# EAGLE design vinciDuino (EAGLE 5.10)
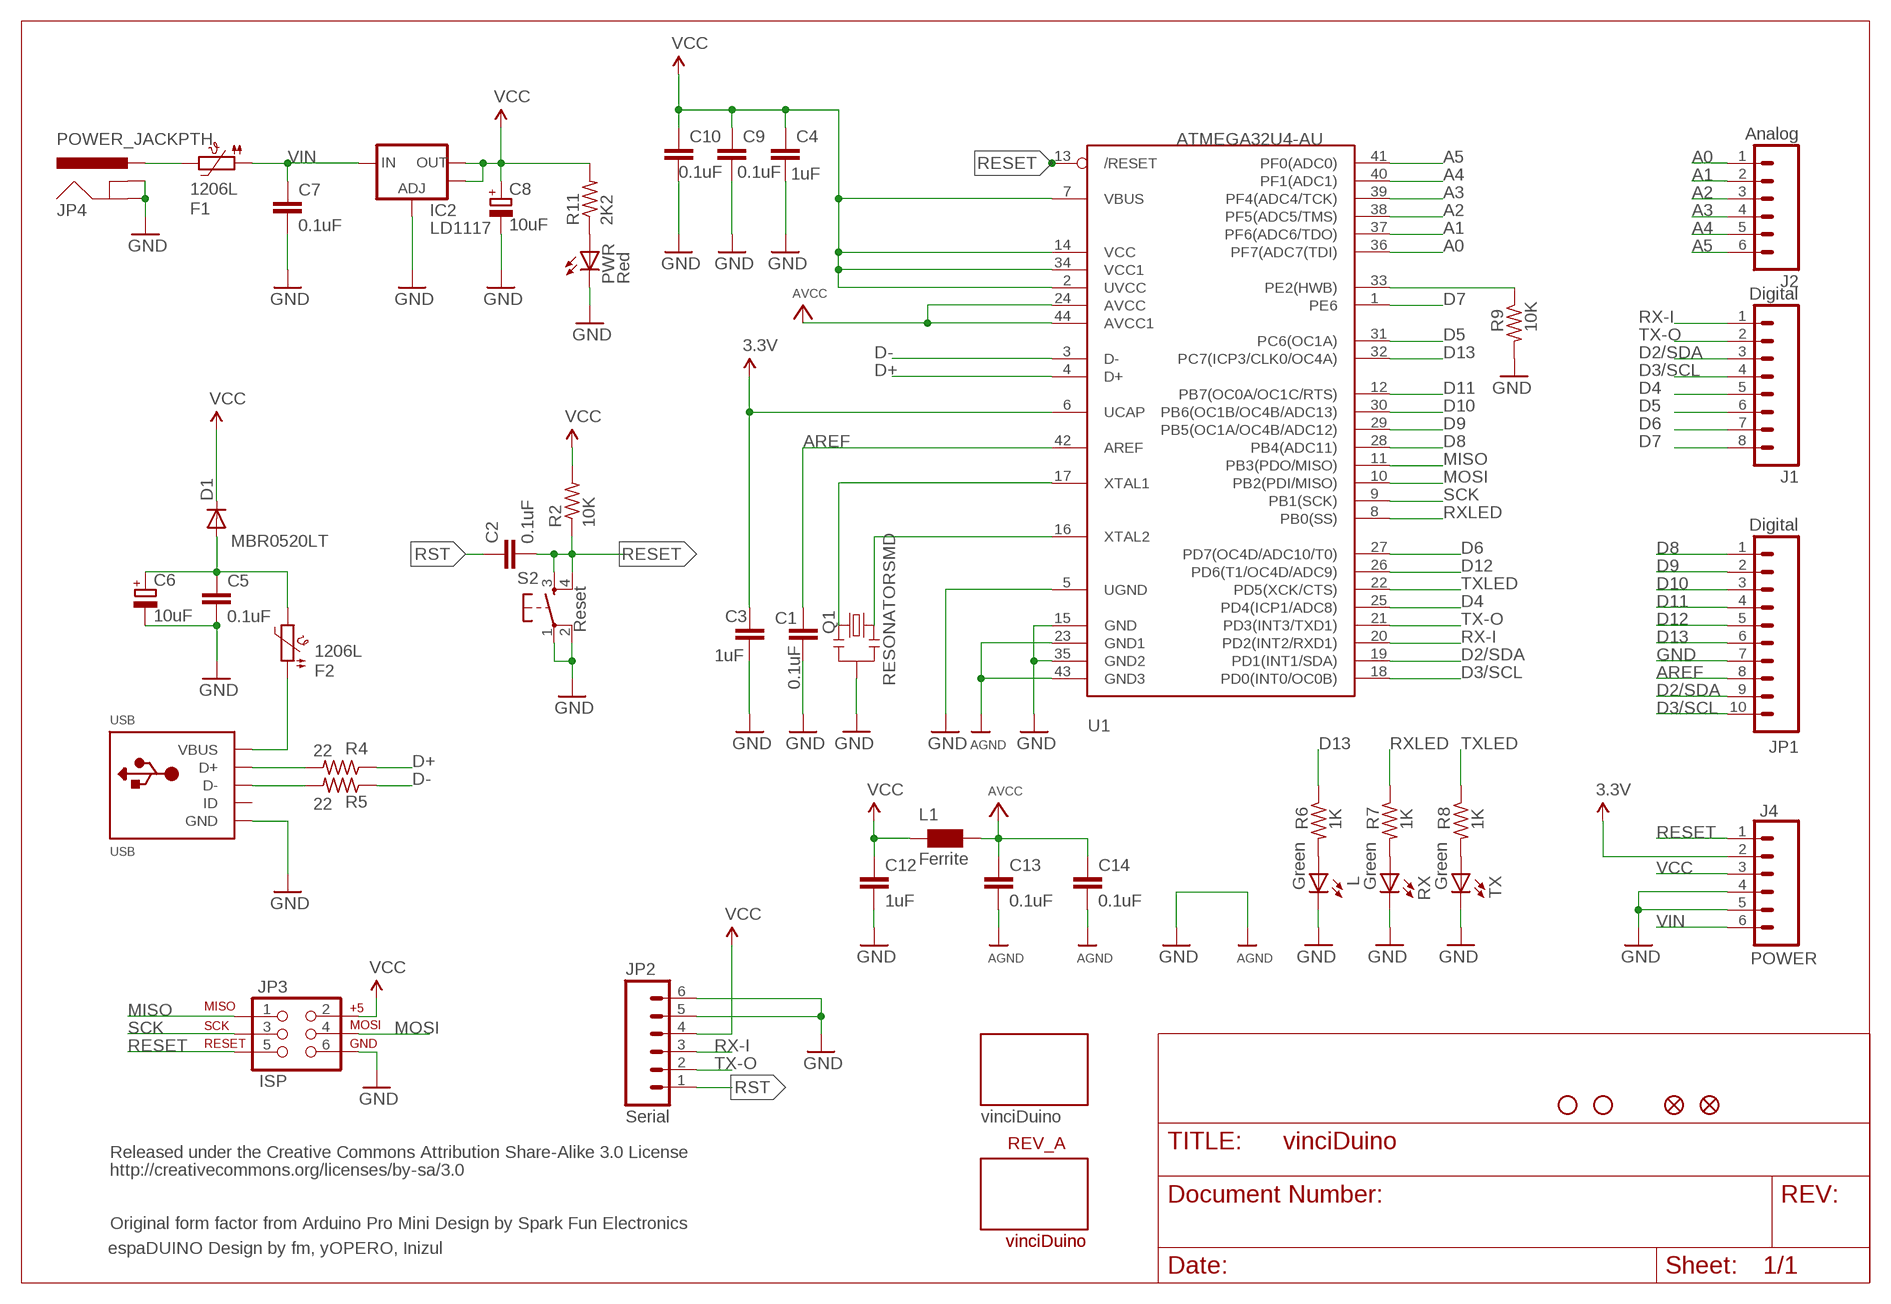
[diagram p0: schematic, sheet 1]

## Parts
C1  0.1uF  CAP1206  [1206]
C2  0.1uF  CAP1206  [1206]
C3  1uF  CAP1206  [1206]
C4  1uF  CAP1206  [1206]
C5  0.1uF  CAP1206  [1206]
C6  10uF  CPOL-EUR/2012-12R  [R/2012-12R]
C7  0.1uF  CAP1206  [1206]
C8  10uF  CPOL-EUR/2012-12R  [R/2012-12R]
C9  0.1uF  CAP1206  [1206]
C10  0.1uF  CAP1206  [1206]
C12  1uF  CAP1206  [1206]
C13  0.1uF  CAP1206  [1206]
C14  0.1uF  CAP1206  [1206]
D1  MBR0520LT  [SOD123]
F1  1206L  PTC1206_L  [1206_PTC]
F2  1206L  PTC1206_L  [1206_PTC]
IC2  LD1117  V_REG_LM1117SOT223  [SOT223]
J1  Digital  M081X08  [1X08]
J2  Analog  M06SIP  [1X06]
J4  POWER  M06SIP  [1X06]
JP1  Digital  M10"  [1X10]
JP2  Serial  M06SIP  [1X06]
JP3  ISP  AVR_SPI_PRG_6PTH  [2X3]
JP4  POWER_JACKPTH  [POWER_JACK_PTH]
L  Green  LED1206  [LED-1206]
L1  Ferrite  WE-CBF_1206  [1206]
PWR  Red  LED1206  [LED-1206]
Q1  RESONATORSMD  [RESONATOR-SMD]
R2  10K  R-US_R1206  [R1206]
R4  22  R-US_R1206  [R1206]
R5  22  R-US_R1206  [R1206]
R6  1K  R-US_R1206  [R1206]
R7  1K  R-US_R1206  [R1206]
R8  1K  R-US_R1206  [R1206]
R9  10K  R-US_R1206  [R1206]
R11  2K2  R-US_R1206  [R1206]
REV_A  vinciDuino  BOARD_INFO_  [ARDUINO_FORUM]
RX  Green  LED1206  [LED-1206]
S2  Reset  TAC_SWITCHSMD  [TACTILE_SWITCH_SMD]
TX  Green  LED1206  [LED-1206]
U1  ATMEGA32U4-AU  [TQFP44]
U$1  VINCIDUINO_  VINCIDUINO_25  [VINCIDUINO]
U$2  FIDUCIAL1X2  [FIDUCIAL-1X2]
U$4  FIDUCIAL1X2  [FIDUCIAL-1X2]
U$9  STAND-OFF  [STAND-OFF]
U$10  STAND-OFF  [STAND-OFF]
USB  USB  USBMINIB  [USB-MINIB]

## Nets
3.3V: C3.1 J4.2 U1.6(UCAP)
A0: J2.1 U1.36(PF7(ADC7(TDI))
A1: J2.2 U1.37(PF6(ADC6/TDO))
A2: J2.3 U1.38(PF5(ADC5/TMS))
A3: J2.4 U1.39(PF4(ADC4/TCK))
A4: J2.5 U1.40(PF1(ADC1))
A5: J2.6 U1.41(PF0(ADC0))
AREF: C1.2 JP1.8 U1.42(AREF)
AVCC: C13.1 C14.1 L1.2 U1.24(AVCC) U1.44(AVCC1)
D2/SDA: J1.3 JP1.9 U1.19(PD1(INT1/SDA))
D3/SCL: J1.4 JP1.10 U1.18(PD0(INT0/OC0B))
D4: J1.5 U1.25(PD4(ICP1/ADC8))
D5: J1.6 U1.31(PC6(OC1A))
D6: J1.7 U1.27(PD7(OC4D/ADC10/T0))
D7: J1.8 U1.1(PE6)
D8: JP1.1 U1.28(PB4(ADC11))
D9: JP1.2 U1.29(PB5(OC1A/OC4B/ADC12))
D10: JP1.3 U1.30(PB6(OC1B/OC4B/ADC13))
D11: JP1.4 U1.12(PB7(OC0A/OC1C/RTS))
D12: JP1.5 U1.26(PD6(T1/OC4D/ADC9))
D13: JP1.6 R6.1 U1.32(PC7(ICP3/CLK0/OC4A))
D+: R4.1 U1.4(D+)
D-: R5.1 U1.3(D-)
GND: C1.1 C3.2 C4.2 C5.2 C6.- C7.2 C8.- C9.2 C10.2 C12.2 C13.2 C14.2 IC2.1(ADJ) J4.4 J4.5 JP1.7 JP2.5 JP2.6 JP3.6 JP4.GND JP4.GNDBREAK L.C PWR.C Q1.2 R9.2 RX.C S2.1 S2.2 TX.C U1.5(UGND) U1.15(GND) U1.23(GND1) U1.35(GND2) U1.43(GND3) USB.GND ; supply symbol labelled AGND
MISO: JP3.1 U1.11(PB3(PDO/MISO))
MOSI: JP3.4 U1.10(PB2(PDI/MISO))
N$1: R7.2 RX.A
N$2: R4.2 USB.D+
N$3: Q1.1 U1.16(XTAL2)
N$4: Q1.3 U1.17(XTAL1)
N$5: R5.2 USB.D-
N$6: R9.1 U1.33(PE2(HWB))
N$7: L.A R6.2
N$10: R8.2 TX.A
N$13: F2.1 USB.VBUS
N$15: F1.2 JP4.PWR
N$38: PWR.A R11.1
RESET: C2.2 J4.1 JP3.5 R2.1 S2.3 S2.4 U1.13(/RESET)
RST: C2.1 JP2.1
RX-I: J1.1 JP2.3 U1.20(PD2(INT2/RXD1))
RXLED: R7.1 U1.8(PB0(SS))
SCK: JP3.3 U1.9(PB1(SCK))
TX-O: J1.2 JP2.2 U1.21(PD3(INT3/TXD1))
TXLED: R8.1 U1.22(PD5(XCK/CTS))
VBUS: C5.1 C6.+ D1.A F2.2
VCC: C4.1 C8.+ C9.1 C10.1 C12.1 D1.C IC2.2(OUT) IC2.4(OUT) J4.3 JP2.4 JP3.2 L1.1 R2.2 R11.2 U1.2(UVCC) U1.7(VBUS) U1.14(VCC) U1.34(VCC1)
VIN [vcc]: C7.1 F1.1 IC2.3(IN) J4.6
Unconnected: USB.ID

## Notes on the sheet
- Released under the Creative Commons Attribution Share-Alike 3.0 License
- http://creativecommons.org/licenses/by-sa/3.0
- Original form factor from Arduino Pro Mini Design by Spark Fun Electronics
- espaDUINO Design by fm, yOPERO, Inizul

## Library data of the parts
C1-C5 C7 C9 C10 C12-C14 = sparkfun_2:CAP: Capacitor
C6 C8 = rcl:CPOL-EU: POLARIZED CAPACITOR, European symbol
D1 = diode:MBR0520LT: SCHOTTKY BARRIER RECTIFIER
F1 F2 = microbuilder:PTC: PTC (Resettable Fuse)
IC2 = SparkFun:V_REG_LM1117: Voltage Regulator LM1117 Standard adjustable voltage regulator but in SMD form. Spark Fun Electronics SKU : COM-00595
J1 = SparkFun:M08: Header 8 Standard 8-pin 0.1" header. Use with straight break away headers (SKU : PRT-00116), right angle break away headers (PRT-00553), swiss pins (PRT-00743), machine pins (PRT-00117), and female headers (PRT-00115).
J2 J4 JP2 = SparkFun:M06: Header 6 Standard 6-pin 0.1" header. Use with straight break away headers (SKU : PRT-00116), right angle break away headers (PRT-00553), swiss pins (PRT-00743), machine pins (PRT-00117), and female headers (PRT-00115). Molex polarized connector foot print use with SKU : PRT-08094 with associated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
JP1 = SparkFun:M10: Header 10 Standard 10-pin 0.1" header. Use with straight break away headers (SKU : PRT-00116), right angle break away headers (PRT-00553), swiss pins (PRT-00743), machine pins (PRT-00117), and female headers (PRT-00115).
JP3 = SparkFun:AVR_SPI_PRG_6: AVR ISP 6 Pin This is the reduced ISP connector for AVR programming. Common on Arduino. This footprint will take up less PCB space and can be used with a 10-pin to 6-pin adapter such as SKU: BOB-08508
JP4 = SparkFun:POWER_JACK: Power Jack This is the standard 5.5mm barrel jack for power. The PTH is the most common, proven, reliable, footprint. All others are experimental. The Slot footprint only works if the mill layer is transmitted to the PCB fab house so be warned. Spark Fun Electronics SKU : PRT-00119. Mating wall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
L PWR RX TX = SparkFun:LED: LEDs
L1 = wuerth-elektronik:WE-CBF: SMD EMI Suppression Ferrite Beads
Q1 = sparkfun_2:RESONATOR: Resonator Small SMD resonator. This is the itty bitty 10/20MHz resonators with built in caps. CSTCE10M0G55 and CSTCE20M0V53. Footprint has been reviewed closely but hasn't been tested yet.
R2 R4-R9 R11 = adafruit:R-US_: RESISTOR, American symbol
REV_A = fmc:BOARD_INFO_
S2 = SparkFun:TAC_SWITCH: Momentary Switch Button commonly used for reset or general input. Spark Fun Electronics SKU : COM-00097
U1 = adafruit:ATMEGA32U4: http://www.ladyada.net/library/eagle
U$1 = fmc:VINCIDUINO_
U$2 U$4 = SparkFun:FIDUCIAL: Fiducial Alignment Points
U$9 U$10 = SparkFun:STAND-OFF: Stand Off
USB = adafruit:USB: USB Connectors USBMINIB - Surface Mount Female Mini-B USB Connector 4UConnector: 06564 By microbuilder.eu Thru-hole RA Female Mini-B USB Connector 4UConnector: 18732 By ladyada.net

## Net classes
1 vcc: width 0.254 mm

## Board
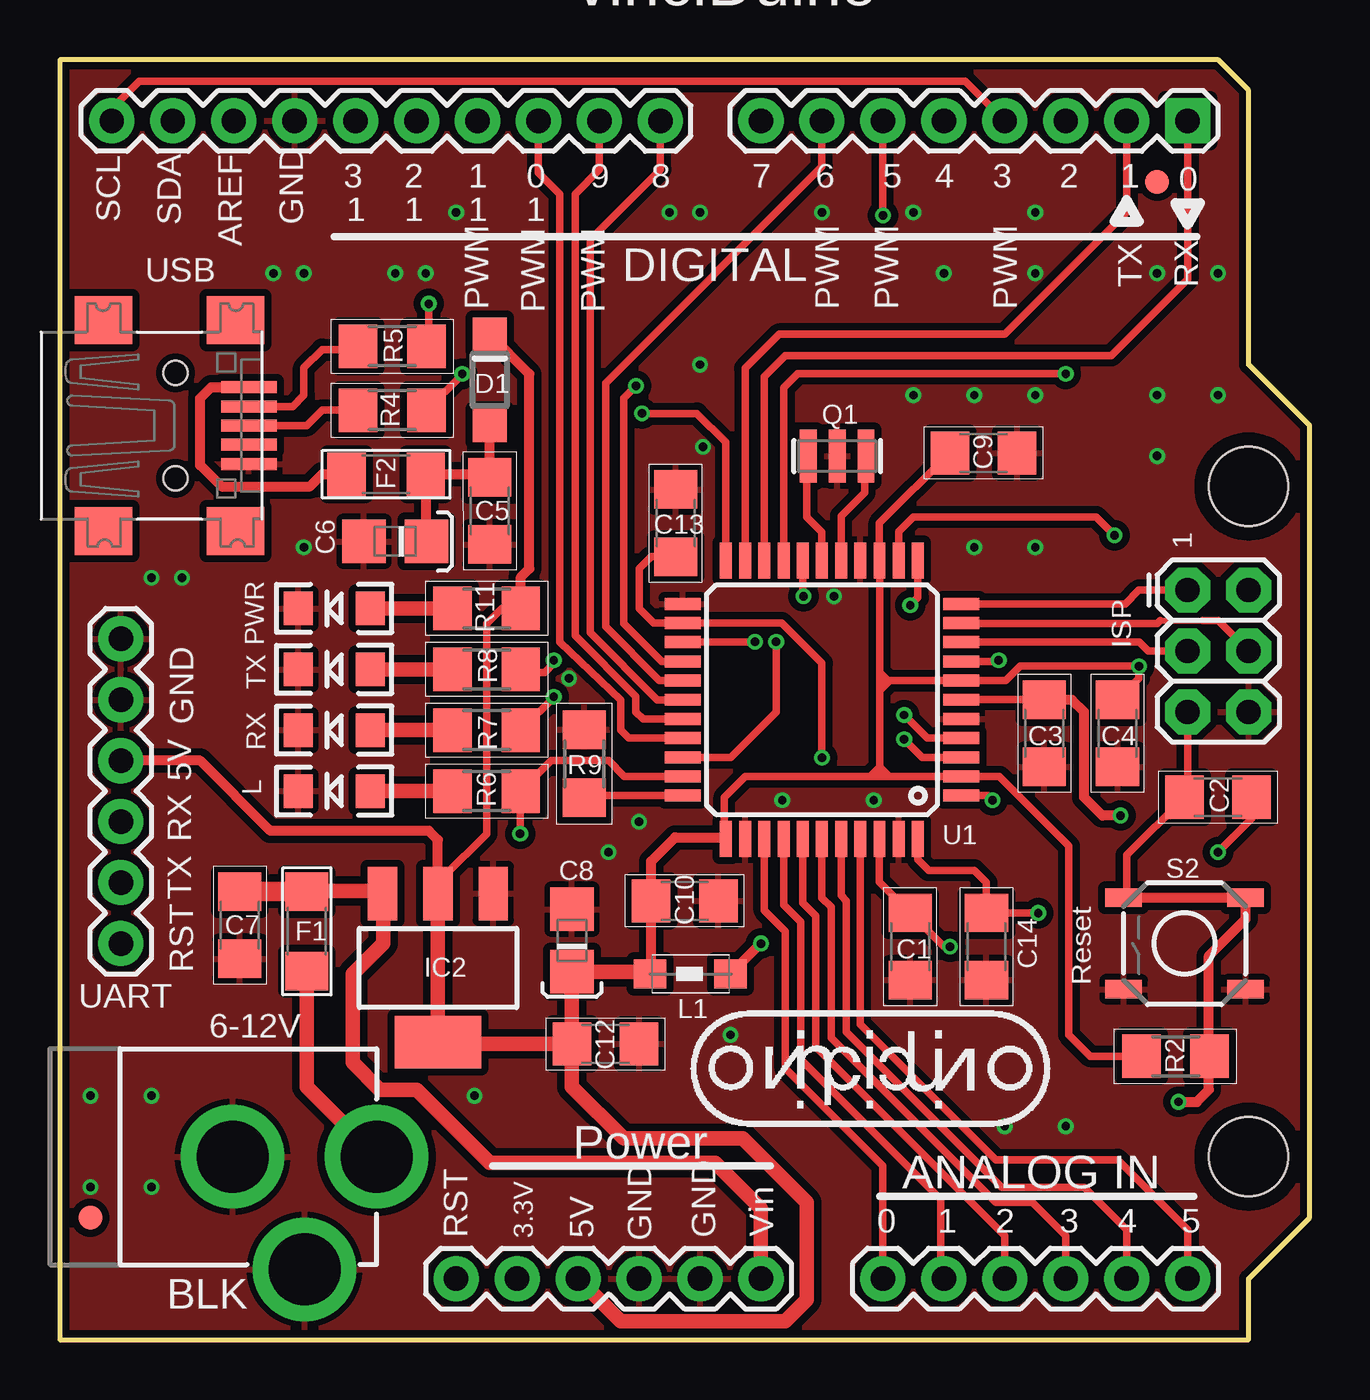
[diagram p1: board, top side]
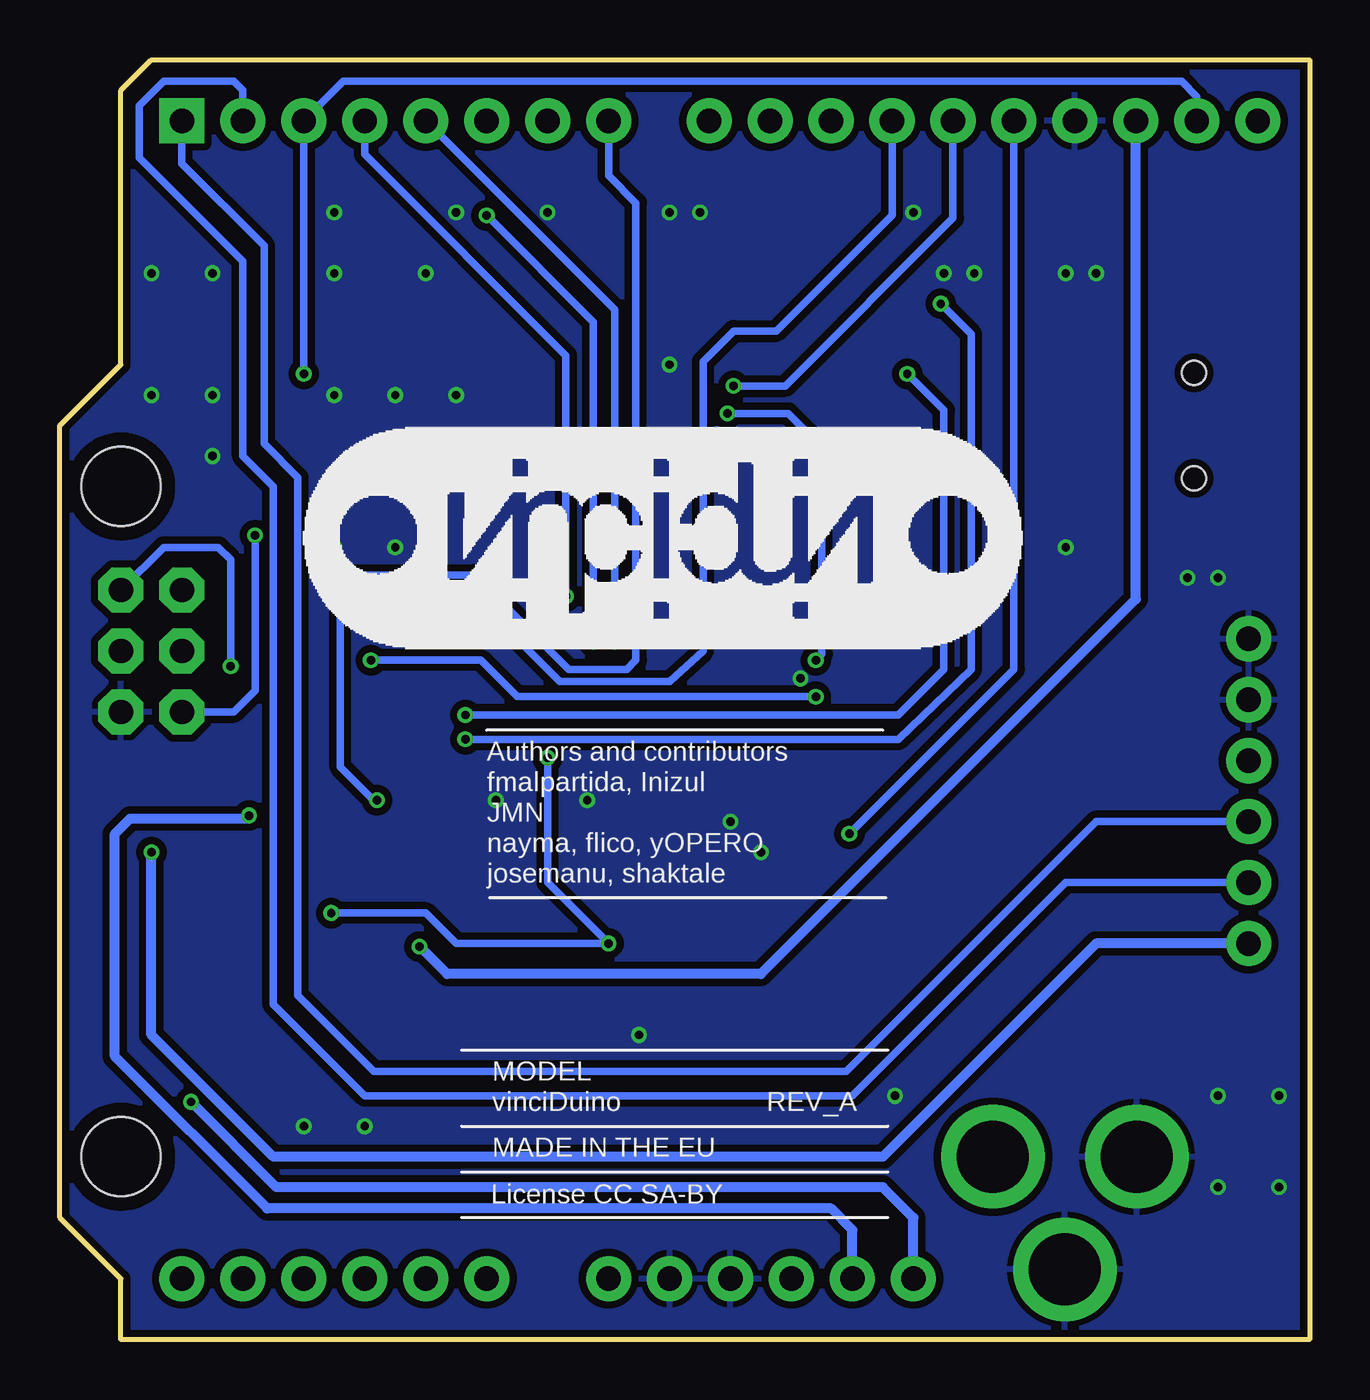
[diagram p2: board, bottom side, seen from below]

Size 52.07 x 53.34 mm. Coordinates in mm from the lower left corner, seen from the top.
Outline: 0,53.34 0,0 49.53,0 49.53,2.54 52.07,5.08 52.07,38.1 49.53,40.64 49.53,52.07 48.26,53.34 0,53.34
Copper layers (1*16): Top 0.0356mm / dielectric 1.5011mm / Bottom 0.0356mm
Design rules "SparkFun_itead_fmc": minimum track width 8mil, minimum drill 0.35mm, track to track 8mil, track to pad 8mil, pad to pad 8mil, via to via 8mil, smd to smd 8mil, copper to edge 10mil, drill to drill 8mil, minimum pad ring 12mil, minimum via ring 6mil, stop-mask expansion 4mil, vias tented up to drill 25mil, thermal gap 10mil

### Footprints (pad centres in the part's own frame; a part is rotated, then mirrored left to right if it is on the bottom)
1206 = smd 1.6 x 1.8: 1 -1.4,0; 2 1.4,0
R/2012-12R = smd 1.8 x 1.8: + 1.302,0; - -1.302,0
SOD123 = smd 1.4 x 1.4: A 1.9,0; C -1.9,0
1206_PTC = smd 1.6 x 1.8: 1 -1.654,0; 2 1.654,0
SOT223 = smd 1.219 x 2.235: 1 -2.311,-3.099; 2 0,-3.099; 3 2.311,-3.099 | smd 3.6 x 2.2: 4 0,3.099
1X08 = drill 1.016 pad 1.88 square: 1 0,0 | drill 1.016 pad 1.88 round: 2 2.54,0; 3 5.08,0; 4 7.62,0; 5 10.16,0; 6 12.7,0; 7 15.24,0; 8 17.78,0
1X06 = drill 1.016 pad 1.88 round: 1 0,0; 2 2.54,0; 3 5.08,0; 4 7.62,0; 5 10.16,0; 6 12.7,0
1X10 = drill 1.016 pad 1.88 round: 1 0,0; 2 2.54,0; 3 5.08,0; 4 7.62,0; 5 10.16,0; 6 12.7,0; 7 15.24,0; 8 17.78,0; 9 20.32,0; 10 22.86,0
2X3 = drill 1.016 pad 1.88 octagon: 1 0,0; 2 0,2.54; 3 2.54,0; 4 2.54,2.54; 5 5.08,0; 6 5.08,2.54
POWER_JACK_PTH = drill 2.997 pad 4.318 round: GND 0,7.7; GNDBREAK 4.7,10.7; PWR 0,13.7
LED-1206 = smd 1.2 x 1.4: A -1.5,0; C 1.5,0
1206' = smd 1.35 x 1.2: 1 -1.7,0; 2 1.65,0
RESONATOR-SMD = smd 0.7 x 2.2: 1 -1.2,0; 2 0,0; 3 1.2,0
R1206 = smd 1.6 x 1.803: 1 -1.422,0; 2 1.422,0
TACTILE_SWITCH_SMD = smd 1.524 x 0.762: 1 -2.54,1.905; 2 2.54,1.905; 3 -2.54,-1.905; 4 2.54,-1.905
TQFP44 = smd 1.5 x 0.5: 1 -5.8,4; 2 -5.8,3.2; 3 -5.8,2.4; 4 -5.8,1.6; 5 -5.8,0.8; 6 -5.8,0; 7 -5.8,-0.8; 8 -5.8,-1.6; 9 -5.8,-2.4; 10 -5.8,-3.2; 11 -5.8,-4; 23 5.8,-4; 24 5.8,-3.2; 25 5.8,-2.4; 26 5.8,-1.6; 27 5.8,-0.8; 28 5.8,0; 29 5.8,0.8; 30 5.8,1.6; 31 5.8,2.4; 32 5.8,3.2; 33 5.8,4 | smd 0.5 x 1.5: 12 -4,-5.8; 13 -3.2,-5.8; 14 -2.4,-5.8; 15 -1.6,-5.8; 16 -0.8,-5.8; 17 0,-5.8; 18 0.8,-5.8; 19 1.6,-5.8; 20 2.4,-5.8; 21 3.2,-5.8; 22 4,-5.8; 34 4,5.8; 35 3.2,5.8; 36 2.4,5.8; 37 1.6,5.8; 38 0.8,5.8; 39 0,5.8; 40 -0.8,5.8; 41 -1.6,5.8; 42 -2.4,5.8; 43 -3.2,5.8; 44 -4,5.8
FIDUCIAL-1X2 = smd 1 x 1: 1 0,0
STAND-OFF = hole 3.302: 0,0
USB-MINIB = smd 0.5 x 2.308: D+ 0,4.064; D- -0.8,4.064; GND 1.6,4.064; ID 0.8,4.064; VBUS -1.6,4.064 | smd 2 x 2.4: GND1 -4.4,-2; GND2 -4.4,3.5; GND3 4.4,3.5; GND4 4.4,-2 | hole 1: -2.2,1; 2.2,1

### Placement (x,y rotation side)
C1  35.43,16.38 90 top
C2  48.26,22.61 180 top
C3  41.02,25.27 270 top
C4  44.07,25.27 270 top
C5  17.91,34.54 270 top
C6  13.97,33.27 0 top
C7  7.49,17.27 270 top
C8  21.34,16.64 270 top
C9  38.48,36.96 0 top
C10  26.04,18.29 0 top
C12  22.73,12.32 0 top
C13  25.65,34.04 90 top
C14  38.61,16.38 270 top
D1  17.91,40.01 270 top
F1  10.29,17.02 270 top
F2  13.59,36.07 0 top
IC2  15.75,15.49 180 top
J1  46.99,50.8 180 top
J2  34.29,2.54 0 top
J4  16.51,2.54 0 top
JP1  25.02,50.8 180 top
JP2  2.54,16.51 90 top
JP3  46.99,31.24 270 top
JP4  -0.51,7.62 270 top
L  11.43,22.86 180 top
L1  Ferrite  [1206']  26.29,15.24 0 top
PWR  11.43,30.48 180 top
Q1  32.38,36.83 180 top
R2  46.48,11.81 180 top
R4  13.84,38.73 180 top
R5  13.84,41.4 180 top
R6  17.78,22.86 180 top
R7  17.78,25.4 180 top
R8  17.78,27.94 180 top
R9  21.84,24 90 top
R11  17.78,30.48 0 top
REV_A  26.67,8.89 0 bottom
RX  11.43,25.4 180 top
S2  46.86,16.51 180 top
TX  11.43,27.94 180 top
U1  31.75,26.67 180 top
U$1  41.91,28.83 0 bottom
U$2  1.27,5.08 0 top
U$4  45.72,48.26 0 top
U$5  [VINCIDUINO_VSMAL]  26.29,8.89 0 top
U$9  49.53,35.56 0 top
U$10  49.53,7.62 0 top
USB  3.81,38.1 270 top

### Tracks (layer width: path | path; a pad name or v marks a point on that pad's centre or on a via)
3.3V  (via drill 0.35)
  Top 0.305: C3.1 U1.6
  Top 0.406: v44.2,21.84 43.43,21.84 42.67,22.61 42.67,26.16 42.16,26.67 C3.1
  Bottom 0.406: J4.2 19.05,4.57 19.94,5.46 43.43,5.46 49.78,11.81 49.78,21.08 49.15,21.72 44.32,21.72 v44.2,21.84
A0
  Top 0.305: U1.36 29.35,17.89 30.23,17.02 30.23,11.3 34.29,7.24 J2.1
A1
  Top 0.305: U1.37 30.15,18.11 30.86,17.4 30.86,11.68 36.7,5.84 36.7,2.67 J2.2
A2
  Top 0.305: U1.38 30.95,18.2 31.5,17.65 31.5,12.19 39.37,4.32 J2.3
A3
  Top 0.305: U1.39 31.75,18.41 32.13,18.03 32.13,12.57 38.99,5.71 40.51,5.71 41.91,4.32 J2.4
A4
  Top 0.305: 32.51,20.83 U1.40 32.55,18.5 32.77,18.29 32.77,12.83 39.24,6.35 42.67,6.35 44.45,4.57 J2.5
A5
  Top 0.305: U1.41 33.35,13.13 38.99,7.49 44.07,7.49 46.99,4.57 J2.6
AREF  (via drill 0.35)
  Top 0.305: C1.2 35.42,17.8 | U1.42 34.15,19.07 C1.2 | v37.08,16.38 36.83,16.38 C1.2
  Bottom 0.406: JP1.8 7.24,30.86 22.86,15.24 35.94,15.24 v37.08,16.38
AVCC  (via drill 0.35)
  Top 0.305: v40.77,17.78 C14.1 38.61,19.05 38.1,19.56 36.2,19.56 35.75,20 U1.44 | C13.1 24.64,32.64 24.13,32.13 24.13,30.48 24.74,29.87 U1.24 30.07,29.87 31.75,28.19 v31.75,24.26 | L1.2 28.32,15.24
  Top 0.406: v29.21,16.51 L1.2
  Bottom 0.305: v29.21,16.51 31.75,19.05 v31.75,24.26 | v29.21,16.51 30.48,17.78 | v40.77,17.78 36.83,17.78 35.56,16.51 v29.21,16.51
D2/SDA  (via drill 0.35)
  Top 0.305: U1.19 30.15,39.67 30.73,40.26 v41.91,40.26
  Bottom 0.305: JP1.9 4.7,51.82 5.33,52.45 40.26,52.45 J1.3 v41.91,40.26
D3/SCL  (via drill 0.35)
  Top 0.305: JP1.10 2.16,51.31 3.3,52.45 37.72,52.45 J1.4 | U1.18 30.95,31.03 v30.99,30.99
  Bottom 0.305: v30.99,30.99 30.99,41.02 39.37,49.4 J1.4
D4  (via drill 0.35)
  Top 0.305: U1.25 28.33,29.07 v28.96,29.08
  Bottom 0.305: v28.96,29.08 28.96,42.93 J1.5
D5  (via drill 0.35)
  Top 0.305: v34.29,46.86 J1.6 | U1.31 27.95,24.27 29.84,26.16 v29.84,29.08
  Bottom 0.305: v29.84,29.08 29.84,42.42 v34.29,46.86
D6
  Top 0.305: 25.23,27.47 U1.27 24.98,27.47 22.73,29.72 22.73,39.88 31.75,48.9 J1.7
D7  (via drill 0.35)
  Top 0.305: U1.1 38.67,22.67 v38.86,22.48
  Bottom 0.305: v38.86,22.48 38.99,22.48 40.39,23.88 40.39,31.5 40.01,31.88 34.8,31.88 30.86,27.94 28.45,27.94 28.07,28.32 28.07,47.37 29.21,48.51 J1.8
D8
  Top 0.305: U1.28 24.89,26.67 22.1,29.46 22.1,45.85 25.02,48.77 JP1.1
D9
  Top 0.305: U1.29 24.3,25.87 24,26.16 24,26.8 21.46,29.34 21.46,47.75 22.48,48.77 JP1.2
D10
  Top 0.305: U1.30 23.7,25.07 23.37,25.4 23.37,26.67 20.83,29.08 20.83,47.75 19.94,48.64 JP1.3
D11  (via drill 0.35)
  Top 0.305: U1.12 35.75,30.92 v35.43,30.61
  Bottom 0.305: v35.43,30.61 34.42,30.61 31.24,27.43 26.67,27.43 25.27,28.7 25.27,40.77 24,42.04 22.23,42.04 17.4,46.86 JP1.4
D12  (via drill 0.35)
  Top 0.305: U1.26 25.07,28.27 23.5,29.84 23.5,39.24 v24,39.75
  Bottom 0.305: v24,39.75 21.84,39.75 14.86,46.74 JP1.5
D13  (via drill 0.35)
  Top 0.305: U1.32 23.52,23.47 22.86,24.13 20.47,24.13 R6.1 19.18,22.84 v19.18,21.08
  Bottom 0.305: JP1.6 12.32,27.94 v19.18,21.08
D+  (via drill 0.35)
  Top 0.305: U1.4 36.14,25.07 v35.18,26.04 | v16.76,40.26 16.76,40.23 R4.1
  Bottom 0.305: v35.18,26.04 17.14,26.04 15.24,27.94 15.24,38.73 v16.76,40.26
D-  (via drill 0.35)
  Top 0.305: U1.3 35.93,24.27 v35.18,25.02 | v15.37,43.18 15.37,41.5 R5.1
  Bottom 0.305: v35.18,25.02 17.14,25.02 14.1,27.94 14.1,41.91 v15.37,43.18
GND  (via drill 0.35)
  other vias: 21.21,27.56 22.86,20.32 26.67,40.64 24.13,21.59 25.4,46.99 35.56,46.99 26.67,46.99 8.89,44.45 10.16,44.45 3.81,31.75 5.08,31.75 39.37,8.89 41.91,8.89 45.72,39.37 48.26,39.37 45.72,36.83 3.81,10.16 3.81,6.35 16.51,46.99 31.75,46.99 45.72,44.45 35.56,39.37 38.1,39.37 26.8,37.21 32.26,30.99 30.1,22.48 33.91,22.48 27.94,12.7 1.27,10.16 1.27,6.35 38.1,33.02 40.64,33.02 40.64,39.37 36.83,44.45 40.64,44.45 40.64,46.99 48.26,44.45 13.97,44.45 15.24,44.45 10.16,33.02 17.27,10.16
  pour Top (isolate 0.305): 0,53.34 52.07,53.34 52.07,0 0,0
  pour Bottom (isolate 0.305): 0,53.34 52.07,53.34 52.07,0 0,0
MISO
  Top 0.305: U1.11 44.39,30.67 44.96,31.24 JP3.1
MOSI
  Top 0.254: 45.85,29.97 47.62,29.97
  Top 0.305: JP3.4 48.26,29.97 47.62,29.97 | 45.85,29.97 45.72,29.84 37.58,29.84 U1.10
N$1
  Top 0.61: RX.A R7.2
N$2
  Top 0.305: USB.D+ 10.29,38.1 10.92,38.73 R4.2
N$3
  Top 0.305: U1.16 32.55,34.33 33.53,35.31 33.53,36.77 Q1.1
N$4
  Top 0.305: U1.17 31.75,33.66 31.11,34.29 31.11,36.76 Q1.3
N$5
  Top 0.305: USB.D- 9.69,38.9 10.16,39.37 10.16,40.51 10.92,41.27 12.29,41.27 R5.2
N$6
  Top 0.305: U1.33 21.93,22.67 R9.1
N$7
  Top 0.61: L.A R6.2
N$10
  Top 0.61: TX.A R8.2
N$13
  Top 0.406: USB.VBUS 6.3,39.7 5.84,39.24 5.84,36.45 6.73,35.56 10.41,35.56 10.92,36.07 F2.1
N$15
  Top 0.61: JP4.PWR 13.19,7.64 10.29,10.54 F1.2
N$38
  Top 0.61: PWR.A R11.1
RESET  (via drill 0.35)
  Top 0.305: U1.13 34.95,33.68 35.56,34.29 43.18,34.29 v43.94,33.53 | JP3.5 46.99,22.74 C2.2 44.45,20.2 44.45,18.54
  Top 0.406: 44.45,18.54 S2.4 S2.3 49.4,17.53 47.88,16 47.88,11.84 R2.1 47.88,11.79 47.88,10.41 47.37,9.91 v46.61,9.91
  Bottom 0.305: v43.94,33.53 43.94,27.05 44.83,26.16 JP3.5
  Bottom 0.406: J4.1 16.51,5.08 17.78,6.35 43.05,6.35 v46.61,9.91
RST  (via drill 0.35)
  Top 0.305: C2.1 49.66,21.72 v48.26,20.32
  Bottom 0.406: JP2.1 8.89,16.51 17.78,7.62 43.18,7.62 48.26,12.7 v48.26,20.32
RX-I
  Top 0.305: U1.20 29.35,40.15 30.23,41.02 43.81,41.02 46.99,44.2 J1.1
  Bottom 0.305: JP2.3 8.89,21.59 19.3,11.18 38.99,11.18 42.16,14.35 42.16,35.94 43.56,37.34 43.56,45.59 46.99,49.02 J1.1
RXLED  (via drill 0.35)
  Top 0.305: U1.8 39.06,28.27 v39.12,28.32 | v20.57,26.8 20.7,26.9 R7.1
  Bottom 0.305: v39.12,28.32 34.54,28.32 33.02,26.8 v20.57,26.8
SCK
  Top 0.305: U1.9 44.97,29.07 45.34,28.7 JP3.3
TX-O
  Top 0.305: J1.2 44.45,46.99 39.37,41.91 29.97,41.91 28.55,40.49 U1.21
  Bottom 0.305: JP2.2 10.16,19.05 19.05,10.16 39.37,10.16 43.18,13.97 43.18,35.56 44.45,36.83 44.45,44.96 48.77,49.28 48.77,51.44 47.75,52.45 44.83,52.45 44.45,52.07 J1.2
TXLED  (via drill 0.35)
  Top 0.305: v20.57,28.32 20.57,28.19 20.19,27.81 19.33,27.81 R8.1 | v24.26,38.61 26.54,38.61 27.75,37.4 U1.22
  Bottom 0.305: v20.57,28.32 20.32,28.57 20.32,37.21 21.72,38.61 v24.26,38.61
VBUS
  Top 0.406: C6.+ 15.27,36.06 F2.2 17.78,36.07 C5.1 D1.A
VCC  (via drill 0.35)
  Top 0.305: 34.29,23.47 28.55,23.47 27.69,22.61 27.69,20.93 U1.34 | 34.29,23.47 U1.2 39.14,23.47 42.04,20.57 42.04,12.7 42.93,11.81 R2.2 | 34.16,23.88 34.16,23.6 34.29,23.47 | 34.16,23.88 34.16,27.05 | 34.16,27.05 34.16,27.3 | 34.16,27.3 34.16,27.81 | 34.16,27.81 34.16,32.46 U1.14 34.15,34.03 C9.1 | 34.16,27.3 34.33,27.47 U1.7 39.41,27.47 40.01,28.07 v44.96,28.07 44.96,27.56 C4.1 | 34.16,27.81 34.54,27.43 34.16,27.05 | 34.16,23.88 34.54,23.5 | 34.16,23.88 33.78,23.5 | R11.2 18.41,30.48 17.78,29.84 17.78,21.08 16,19.3 16,18.85 IC2.2
  Top 0.406: JP2.4 5.84,24.13 8.76,21.21 15.37,21.21 15.75,20.83 IC2.2 | R11.2 19.2,31.77 19.56,32.13 19.56,40.25 D1.C | 27.69,20.93 25.63,20.93 24.64,19.94 C10.1 | C10.1 | C10.1 24.64,15.29 L1.1
  Top 0.61: 21.46,2.41 J4.3 23.37,0.76 30.23,0.76 31.11,1.65 31.11,5.71 28.45,8.38 23.5,8.38 21.34,10.54 C12.1 | IC2.2 IC2.4 15.75,12.7 16.51,12.7 16.51,12.32 C12.1 | C12.1 C8.+ 24.59,15.34 L1.1
  Bottom 0.305: v44.96,28.07 44.96,32.51 45.47,33.02 47.75,33.02 JP3.2
VIN
  Top 0.61: J4.6 29.21,5.46 27.3,7.37 17.91,7.37 14.86,10.41 13.34,10.41 12.19,11.56 12.19,15.24 13.46,16.51 13.46,18.57 IC2.3 13.72,18.69 10.29,18.69 F1.1
  Top 0.813: F1.1 C7.1

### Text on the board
tPlace: Released under the Creative Commons Attribution Share-Alike 3.0 License | http://creativecommons.org/licenses/by-sa/3.0 | vinciDuino | 3 | 2 | 1 | 0 | 9 | 8 | 7 | 6 | 5 | 4 | 3 | 2 | 1 | 0 | SCL | 1 | 1 | 1 | 1 | SDA | AREF | GND | DIGITAL | TX | RX | PWM | PWM | PWM | PWM | PWM | PWM | 1 | ISP | GND | 5V | RX | TX | UART | RST | Reset | 6-12V | Power | ANALOG IN | RST | 3.3V | 5V | GND | GND | Vin | 0 | 1 | 2 | 3 | 4 | 5 | BLK
bPlace: Authors and contributors | fmalpartida, Inizul | JMN | nayma, flico, yOPERO | josemanu, shaktale
tValues: DNP | DNP | JST-Right Angle | DNP | Production: DNP | Production: DNP | Proto: 2x3 male header up | DNP | DNP | DNP | Arduino Pro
